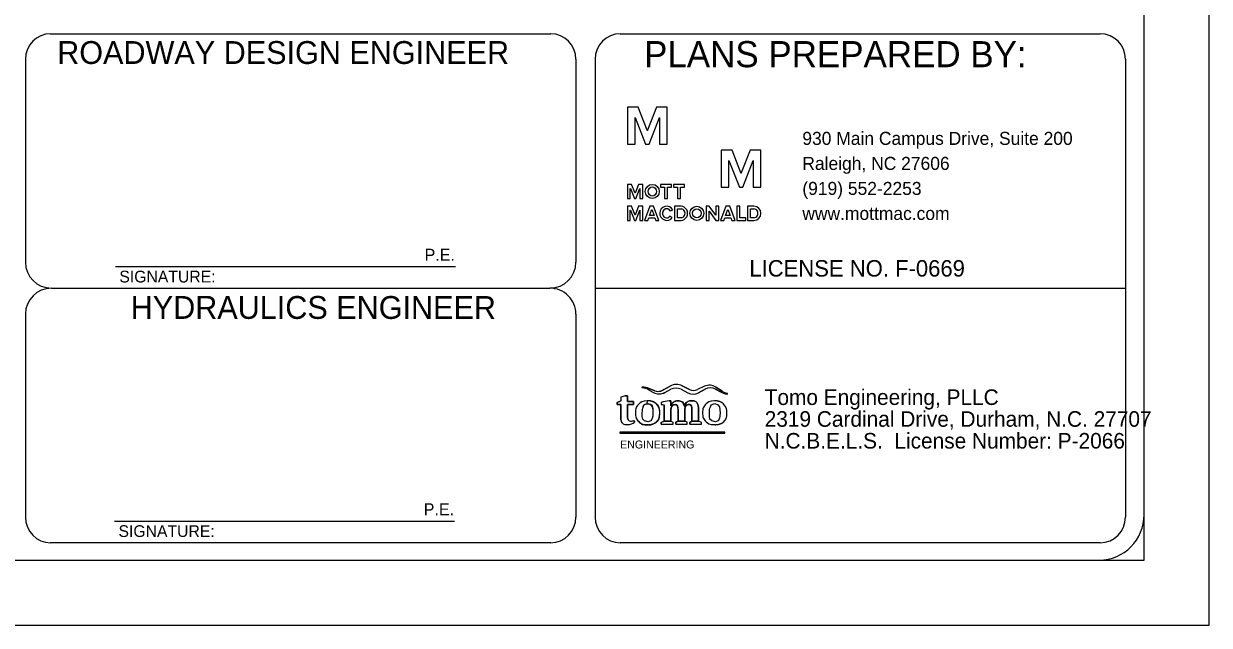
# Model space of a CAD drawing. Extents: x 2538775 to 2540754, y 826823 to 828055.
# Drawn here: x 2540020.2 to 2540474.9, y 826846.8 to 827077.6 of the extents above; entities that cross this region are included whole.
import ezdxf

# ---------------------------------------------------------------- set-up
doc = ezdxf.new("R2010")
doc.units = 0
for name, color, linetype in [('Default', 7, 'Continuous'), ('Old_Level_2', 7, 'Continuous'), ('Old_Level_3', 7, 'Continuous'), ('Old_Level_40', 7, 'Continuous'), ('Old_Level_62', 7, 'Continuous'), ('Old_Level_63', 7, 'Continuous'), ('Sheet Title CELL', 7, 'Continuous')]:
    doc.layers.add(name, color=color, linetype=linetype)

msp = doc.modelspace()

# ---------------------------------------------------------------- linework, layer by layer
at = {"layer": 'Default'}
for p, q in [((2540260.09, 826937.08), (2540261.69, 826936.18)), ((2540260.09, 826937.08), (2540261.69, 826936.18)), ((2540260.12, 826937.66), (2540262.2, 826936.82)), ((2540262.2, 826936.82), (2540260.12, 826937.66)), ((2540265.32, 826937.03), (2540268.13, 826938.62)), ((2540268.13, 826938.62), (2540265.32, 826937.03)), ((2540266.02, 826936.12), (2540268.42, 826937.37)), ((2540266.02, 826936.12), (2540268.42, 826937.37)), ((2540272.33, 826937.38), (2540274.96, 826936.03)), ((2540272.33, 826937.38), (2540274.96, 826936.03)), ((2540272.72, 826938.74), (2540275.53, 826937.33)), ((2540275.53, 826937.33), (2540272.72, 826938.74)), ((2540281.32, 826938.54), (2540278.62, 826937.29)), ((2540281.32, 826938.54), (2540278.62, 826937.29)), ((2540281.52, 826937.39), (2540278.99, 826936.06)), ((2540278.99, 826936.06), (2540281.52, 826937.39)), ((2540287.38, 826936.41), (2540285.57, 826937.38)), ((2540285.57, 826937.38), (2540287.38, 826936.41)), ((2540285.69, 826938.22), (2540288.07, 826936.65)), ((2540288.07, 826936.65), (2540285.69, 826938.22)), ((2540247.86, 826932.3), (2540249.26, 826932.91)), ((2540249.26, 826932.91), (2540247.86, 826932.3)), ((2540249.26, 826934.3), (2540249.26, 826932.91)), ((2540249.26, 826934.3), (2540249.26, 826932.91)), ((2540250.93, 826934.9), (2540251.78, 826934.9)), ((2540251.78, 826934.9), (2540250.93, 826934.9)), ((2540251.78, 826934.9), (2540251.78, 826932.73)), ((2540251.78, 826932.73), (2540251.78, 826934.9)), ((2540251.78, 826932.73), (2540254.05, 826932.73)), ((2540254.05, 826932.73), (2540251.78, 826932.73)), ((2540259.35, 826932.98), (2540259.23, 826931.85)), ((2540259.35, 826932.98), (2540259.35, 826932.98)), ((2540267.76, 826932.92), (2540268.35, 826932.92)), ((2540268.35, 826932.92), (2540267.76, 826932.92)), ((2540268.35, 826932.92), (2540268.35, 826930.98)), ((2540268.35, 826930.98), (2540268.35, 826932.92)), ((2540247.86, 826931.57), (2540247.86, 826932.3)), ((2540247.86, 826932.3), (2540247.86, 826931.57)), ((2540249.24, 826931.57), (2540247.86, 826931.57)), ((2540247.86, 826931.57), (2540249.24, 826931.57)), ((2540249.24, 826925.69), (2540249.24, 826931.57)), ((2540249.24, 826931.57), (2540249.24, 826925.69)), ((2540264.71, 826932.31), (2540264.71, 826931.61)), ((2540264.71, 826932.31), (2540264.71, 826931.61)), ((2540251.14, 826923.82), (2540251.85, 826923.83)), ((2540251.14, 826923.82), (2540251.85, 826923.83)), ((2540254.36, 826925.41), (2540254.48, 826924.81)), ((2540254.48, 826924.81), (2540254.36, 826925.41)), ((2540264.71, 826924.69), (2540265.82, 826925.12)), ((2540265.82, 826925.12), (2540264.71, 826924.69)), ((2540264.71, 826924.01), (2540264.71, 826924.69)), ((2540264.71, 826924.69), (2540264.71, 826924.69)), ((2540264.71, 826924.69), (2540264.71, 826924.01)), ((2540264.71, 826924.01), (2540269.23, 826924.01)), ((2540264.71, 826924.01), (2540269.23, 826924.01)), ((2540268.37, 826925.12), (2540265.82, 826925.12)), ((2540269.23, 826924.69), (2540268.37, 826925.12)), ((2540269.23, 826924.69), (2540268.37, 826925.12)), ((2540269.23, 826924.01), (2540269.23, 826924.69)), ((2540269.23, 826924.69), (2540269.23, 826924.69)), ((2540269.23, 826924.01), (2540269.23, 826924.69)), ((2540270.09, 826924.71), (2540270.09, 826924.71)), ((2540270.27, 826924.71), (2540271.14, 826925.14)), ((2540271.14, 826925.14), (2540270.27, 826924.71)), ((2540270.27, 826924.03), (2540270.27, 826924.71)), ((2540270.27, 826924.71), (2540270.27, 826924.03)), ((2540270.27, 826924.03), (2540274.62, 826924.03)), ((2540270.27, 826924.03), (2540274.62, 826924.03)), ((2540273.7, 826925.14), (2540271.14, 826925.14)), ((2540274.62, 826924.71), (2540273.7, 826925.14)), ((2540274.62, 826924.71), (2540273.7, 826925.14)), ((2540274.62, 826924.03), (2540274.62, 826924.71)), ((2540274.62, 826924.71), (2540274.62, 826924.71)), ((2540274.62, 826924.03), (2540274.62, 826924.71)), ((2540275.39, 826924.68), (2540275.39, 826924.68)), ((2540275.67, 826924.68), (2540276.5, 826925.12)), ((2540276.5, 826925.12), (2540275.67, 826924.68)), ((2540275.67, 826924.01), (2540275.67, 826924.68)), ((2540275.67, 826924.68), (2540275.67, 826924.01)), ((2540275.67, 826924.01), (2540280.19, 826924.01)), ((2540275.67, 826924.01), (2540280.19, 826924.01)), ((2540279.05, 826925.12), (2540276.5, 826925.12)), ((2540280.19, 826924.68), (2540279.05, 826925.12)), ((2540280.19, 826924.68), (2540279.05, 826925.12)), ((2540279.91, 826924.68), (2540279.91, 826924.68)), ((2540280.19, 826924.01), (2540280.19, 826924.68)), ((2540280.19, 826924.01), (2540280.19, 826924.68)), ((2540289.15, 826920.95), (2540248.88, 826920.94)), ((2540289.15, 826920.95), (2540248.88, 826920.94)), ((2540248.88, 826920.94), (2540248.88, 826920.56)), ((2540248.88, 826920.94), (2540248.88, 826920.56)), ((2540248.88, 826920.56), (2540289.15, 826920.56)), ((2540248.88, 826920.56), (2540289.15, 826920.56)), ((2540289.15, 826920.56), (2540289.15, 826920.95)), ((2540289.15, 826920.56), (2540289.15, 826920.95)), ((2540289.15, 826920.56), (2540289.15, 826920.56))]:
    msp.add_line(p, q, dxfattribs=at)
for points in [[(2540254.05, 826932.73), (2540254.05, 826931.57), (2540251.76, 826931.57), (2540251.76, 826926.49)], [(2540251.76, 826926.49), (2540251.76, 826931.57), (2540254.05, 826931.57), (2540254.05, 826932.73)], [(2540268.37, 826929.76), (2540268.37, 826925.12), (2540265.82, 826925.12), (2540265.82, 826931.43)], [(2540265.82, 826931.43), (2540265.82, 826925.12), (2540268.37, 826925.12), (2540268.37, 826929.76)], [(2540273.7, 826929.51), (2540273.7, 826925.14), (2540271.14, 826925.14), (2540271.14, 826929.12)], [(2540271.14, 826929.12), (2540271.14, 826925.14), (2540273.7, 826925.14), (2540273.7, 826929.51)], [(2540279.05, 826929.53), (2540279.05, 826925.12), (2540276.5, 826925.12), (2540276.5, 826929.07)], [(2540276.5, 826929.07), (2540276.5, 826925.12), (2540279.05, 826925.12), (2540279.05, 826929.53)]]:
    msp.add_lwpolyline(points, dxfattribs=at)
for centre, radius, start, end in [((2540257.4, 826938.09), 0.101, 89.4701, 262.0204), ((2540257.4, 826938.09), 0.101, 89.4701, 262.0204), ((2540256.31, 826930.34), 7.72, 60.7255, 82.0204), ((2540256.31, 826930.34), 7.72, 60.7255, 82.0204), ((2540257.33, 826930.67), 7.52, 68.211, 89.4701), ((2540257.33, 826930.67), 7.52, 68.211, 89.4701), ((2540263.54, 826940.18), 3.61, 248.211, 308.9356), ((2540263.54, 826940.18), 3.61, 248.211, 299.5442), ((2540270.54, 826934.37), 4.89, 63.4105, 119.5442), ((2540270.54, 826934.37), 4.89, 63.4105, 119.5442), ((2540270.39, 826933.6), 4.26, 62.7919, 117.5568), ((2540270.39, 826933.6), 4.26, 62.7919, 117.5568), ((2540277.12, 826940.51), 3.56, 243.4105, 294.8953), ((2540277.12, 826940.51), 3.56, 243.4105, 294.8953), ((2540283.21, 826934.47), 4.49, 56.5776, 114.8953), ((2540283.21, 826934.47), 4.49, 56.5776, 114.8953), ((2540283.53, 826933.57), 4.32, 61.9151, 117.8233), ((2540283.53, 826933.57), 4.32, 61.9151, 117.8233), ((2540252.8, 826927.1), 8.02, 103.443, 116.1707), ((2540252.8, 826927.1), 8.02, 103.443, 116.1707), ((2540263.91, 826940.15), 4.55, 240.7255, 299.8298), ((2540263.91, 826940.15), 4.55, 240.7255, 297.5568), ((2540268.26, 826922.63), 10.31, 92.7753, 110.1143), ((2540268.26, 826922.63), 10.31, 92.7753, 110.1143), ((2540276.95, 826939.91), 4.36, 242.7919, 297.8233), ((2540276.95, 826939.91), 4.36, 242.7919, 297.8233), ((2540291.3, 826943.75), 8.32, 241.9151, 260.5433), ((2540291.3, 826943.75), 8.32, 241.9151, 260.5433), ((2540291.34, 826941.6), 5.94, 236.5776, 256.8197), ((2540291.34, 826941.6), 5.94, 236.5776, 256.8197), ((2540289.96, 826935.68), 0.139, 260.5433, 76.8197), ((2540289.96, 826935.68), 0.139, 260.5433, 76.8197), ((2540273.3, 826982.39), 51.51, 260.395, 261.6509), ((2540273.3, 826982.39), 51.51, 260.395, 261.6509), ((2540251.11, 826925.69), 1.86, 180, 270.9178), ((2540251.11, 826925.69), 1.86, 180, 270.9178), ((2540253.23, 826926.49), 1.47, 180, 216.038), ((2540253.23, 826926.49), 1.47, 180, 214.5443), ((2540251.79, 826928.02), 4.19, 270.9178, 309.9754), ((2540251.79, 826928.02), 4.19, 270.9178, 309.9754), ((2540252.89, 826926.25), 1.04, 214.2431, 269.2019), ((2540252.89, 826926.25), 1.04, 214.2431, 269.2019), ((2540252.94, 826930.15), 4.95, 269.2019, 286.6975), ((2540252.94, 826930.15), 4.95, 269.2019, 286.6975)]:
    msp.add_arc(centre, radius, start, end, dxfattribs=at)
for points, degree in [([(2540259.35, 826932.98), (2540261.23, 826932.98), (2540262.71, 826931.94), (2540264.13, 826930.56), (2540264.13, 826928.32), (2540264.1, 826925.83), (2540262.7, 826924.69), (2540261.18, 826923.69), (2540259.35, 826923.82), (2540257.36, 826923.69), (2540256.1, 826924.98), (2540254.84, 826926.28), (2540254.84, 826928.34), (2540254.84, 826930.44), (2540256.13, 826931.71), (2540257.42, 826932.98), (2540259.35, 826932.98)], 3), ([(2540259.35, 826932.98), (2540257.42, 826932.98), (2540256.13, 826931.71), (2540254.84, 826930.44), (2540254.84, 826928.34), (2540254.84, 826926.28), (2540256.1, 826924.98), (2540257.36, 826923.69), (2540259.35, 826923.82)], 3), ([(2540262.71, 826931.94), (2540261.23, 826932.98), (2540259.35, 826932.98)], 2), ([(2540268.35, 826930.98), (2540269.08, 826932.88), (2540271.15, 826932.95), (2540273.19, 826932.8), (2540273.57, 826930.89), (2540274.4, 826932.93), (2540276.46, 826932.97), (2540278.03, 826932.92), (2540278.63, 826931.84), (2540279.07, 826930.97), (2540279.05, 826929.53)], 3), ([(2540271.15, 826932.95), (2540269.08, 826932.88), (2540268.35, 826930.98)], 2), ([(2540273.57, 826930.89), (2540273.19, 826932.8), (2540271.15, 826932.95)], 2), ([(2540279.05, 826929.53), (2540279.07, 826930.97), (2540278.63, 826931.84), (2540278.03, 826932.92), (2540276.46, 826932.97), (2540274.4, 826932.93), (2540273.57, 826930.89)], 3), ([(2540285.1, 826932.98), (2540283.17, 826932.98), (2540281.88, 826931.71), (2540280.59, 826930.44), (2540280.59, 826928.34), (2540280.59, 826926.28), (2540281.85, 826924.98), (2540283.12, 826923.69), (2540285.1, 826923.82)], 3), ([(2540288.46, 826931.94), (2540286.98, 826932.98), (2540285.1, 826932.98)], 2), ([(2540259.7, 826924.84), (2540257.25, 826925.04), (2540257.46, 826928.37), (2540257.46, 826929.69), (2540257.73, 826930.5), (2540258.18, 826931.77), (2540259.52, 826931.89)], 3), ([(2540259.7, 826924.84), (2540261.52, 826925.2), (2540261.43, 826928.42), (2540261.59, 826931.51), (2540259.52, 826931.89), (2540258.18, 826931.77), (2540257.73, 826930.5), (2540257.46, 826929.69), (2540257.46, 826928.37), (2540257.25, 826925.04), (2540259.7, 826924.84)], 3), ([(2540259.52, 826931.89), (2540261.59, 826931.51), (2540261.43, 826928.42), (2540261.52, 826925.2), (2540259.7, 826924.84)], 3), ([(2540262.7, 826924.69), (2540264.1, 826925.83), (2540264.13, 826928.32), (2540264.13, 826930.56), (2540262.71, 826931.94)], 3), ([(2540271.14, 826929.12), (2540271.17, 826930.22), (2540270.96, 826930.72), (2540270.85, 826931.52), (2540269.91, 826931.52), (2540268.64, 826931.33), (2540268.37, 826929.76)], 3), ([(2540268.37, 826929.76), (2540268.64, 826931.33), (2540269.91, 826931.52)], 2), ([(2540269.91, 826931.52), (2540270.85, 826931.52), (2540270.96, 826930.72)], 2), ([(2540270.96, 826930.72), (2540271.17, 826930.22), (2540271.14, 826929.12)], 2), ([(2540276.5, 826929.07), (2540276.5, 826929.94), (2540276.4, 826930.35), (2540276.22, 826931.51), (2540275.25, 826931.51), (2540273.83, 826931.39), (2540273.7, 826929.51)], 3), ([(2540273.7, 826929.51), (2540273.83, 826931.39), (2540275.25, 826931.51), (2540276.22, 826931.51), (2540276.4, 826930.35), (2540276.5, 826929.94), (2540276.5, 826929.07)], 3), ([(2540285.46, 826924.84), (2540283.01, 826925.04), (2540283.22, 826928.37), (2540283.22, 826929.69), (2540283.49, 826930.5), (2540283.93, 826931.77), (2540285.28, 826931.89)], 3), ([(2540285.28, 826931.89), (2540287.34, 826931.51), (2540287.18, 826928.42), (2540287.27, 826925.2), (2540285.46, 826924.84)], 3), ([(2540288.46, 826924.69), (2540289.85, 826925.83), (2540289.88, 826928.32), (2540289.89, 826930.56), (2540288.46, 826931.94)], 3), ([(2540259.35, 826923.82), (2540261.18, 826923.69), (2540262.7, 826924.69)], 2), ([(2540285.1, 826923.82), (2540286.94, 826923.69), (2540288.46, 826924.69)], 2)]:
    msp.add_open_spline(points, degree=degree, dxfattribs=at)
at = {"layer": 'Old_Level_2'}
for p, q in [((2540255.92, 827045.56), (2540251.73, 827045.56)), ((2540251.73, 827045.56), (2540251.73, 827031.43)), ((2540259.34, 827036.83), (2540255.92, 827045.56)), ((2540262.84, 827045.56), (2540259.42, 827036.83)), ((2540260.03, 827031.43), (2540264, 827041.63)), ((2540267.03, 827045.56), (2540262.84, 827045.56)), ((2540264, 827041.63), (2540264.05, 827041.63)), ((2540264.05, 827041.63), (2540264.05, 827031.43)), ((2540267.03, 827031.43), (2540267.03, 827045.56)), ((2540254.71, 827031.43), (2540254.71, 827041.59)), ((2540254.71, 827041.59), (2540254.75, 827041.59)), ((2540254.75, 827041.59), (2540258.73, 827031.43)), ((2540259.33, 827036.7), (2540259.34, 827036.83)), ((2540259.42, 827036.7), (2540259.33, 827036.7)), ((2540259.42, 827036.83), (2540259.42, 827036.7)), ((2540251.73, 827031.43), (2540254.71, 827031.43)), ((2540258.73, 827031.43), (2540260.03, 827031.43)), ((2540264.05, 827031.43), (2540267.03, 827031.43)), ((2540291.85, 827029.1), (2540287.66, 827029.1)), ((2540287.66, 827029.1), (2540287.66, 827014.97)), ((2540295.27, 827020.37), (2540291.85, 827029.1)), ((2540298.77, 827029.1), (2540295.35, 827020.37)), ((2540302.96, 827029.1), (2540298.77, 827029.1)), ((2540302.96, 827014.97), (2540302.96, 827029.1)), ((2540290.64, 827014.97), (2540290.64, 827025.12)), ((2540290.64, 827025.12), (2540290.69, 827025.12)), ((2540290.69, 827025.12), (2540294.66, 827014.97)), ((2540295.96, 827014.97), (2540299.94, 827025.17)), ((2540299.94, 827025.17), (2540299.98, 827025.17)), ((2540299.98, 827025.17), (2540299.98, 827014.97)), ((2540295.27, 827020.24), (2540295.27, 827020.37)), ((2540295.35, 827020.24), (2540295.27, 827020.24)), ((2540295.35, 827020.37), (2540295.35, 827020.24)), ((2540253.33, 827015.96), (2540251.73, 827015.96)), ((2540251.73, 827015.96), (2540251.73, 827010.56)), ((2540252.85, 827010.56), (2540252.85, 827014.45)), ((2540252.85, 827014.45), (2540252.9, 827014.45)), ((2540252.85, 827014.45), (2540252.9, 827014.45)), ((2540252.9, 827014.45), (2540254.41, 827010.56)), ((2540254.67, 827012.59), (2540253.33, 827015.96)), ((2540256.01, 827015.96), (2540254.67, 827012.59)), ((2540254.93, 827010.56), (2540256.44, 827014.45)), ((2540257.61, 827015.96), (2540256.01, 827015.96)), ((2540256.44, 827014.45), (2540256.48, 827014.45)), ((2540256.44, 827014.45), (2540256.48, 827014.45)), ((2540256.44, 827014.45), (2540256.48, 827014.45)), ((2540256.48, 827014.45), (2540256.48, 827010.56)), ((2540257.61, 827010.56), (2540257.61, 827015.96)), ((2540257.61, 827010.56), (2540257.61, 827015.96)), ((2540287.66, 827014.97), (2540290.64, 827014.97)), ((2540294.66, 827014.97), (2540295.96, 827014.97)), ((2540299.98, 827014.97), (2540302.96, 827014.97)), ((2540251.73, 827010.56), (2540252.85, 827010.56)), ((2540254.41, 827010.56), (2540254.93, 827010.56)), ((2540256.48, 827010.56), (2540257.61, 827010.56)), ((2540253.33, 827007.58), (2540251.73, 827007.58)), ((2540251.73, 827007.58), (2540251.73, 827002.18)), ((2540252.85, 827002.18), (2540252.85, 827006.07)), ((2540252.85, 827006.07), (2540252.9, 827006.07)), ((2540252.9, 827006.07), (2540254.41, 827002.18)), ((2540254.67, 827004.21), (2540253.33, 827007.58)), ((2540256.01, 827007.58), (2540254.67, 827004.21)), ((2540254.93, 827002.18), (2540256.44, 827006.07)), ((2540257.61, 827007.58), (2540256.01, 827007.58)), ((2540256.44, 827006.07), (2540256.48, 827006.07)), ((2540256.48, 827006.07), (2540256.48, 827002.18)), ((2540257.61, 827002.18), (2540257.61, 827007.58)), ((2540268.15, 827005.82), (2540269.1, 827006.25)), ((2540268.15, 827005.82), (2540269.1, 827006.25)), ((2540272.3, 827007.57), (2540269.83, 827007.58)), ((2540269.83, 827007.58), (2540269.83, 827004.78)), ((2540270.96, 827003.21), (2540270.96, 827006.58)), ((2540270.96, 827006.58), (2540272.3, 827006.58)), ((2540297.79, 827007.58), (2540297.79, 827007.58)), ((2540300.26, 827007.58), (2540297.79, 827007.58)), ((2540297.79, 827007.58), (2540297.79, 827004.78)), ((2540298.92, 827003.21), (2540298.92, 827006.58)), ((2540298.92, 827006.58), (2540300.26, 827006.58)), ((2540300.26, 827006.54), (2540300.26, 827006.54)), ((2540251.73, 827002.18), (2540252.85, 827002.18)), ((2540254.41, 827002.18), (2540254.93, 827002.18)), ((2540256.48, 827002.18), (2540257.61, 827002.18)), ((2540268.95, 827003.29), (2540268.02, 827003.74)), ((2540268.95, 827003.29), (2540268.02, 827003.74)), ((2540269.83, 827004.78), (2540269.83, 827002.18)), ((2540269.83, 827002.18), (2540272.3, 827002.18)), ((2540272.3, 827003.21), (2540270.96, 827003.21)), ((2540297.79, 827004.78), (2540297.79, 827002.18)), ((2540297.79, 827002.18), (2540300.26, 827002.18)), ((2540300.26, 827003.21), (2540298.92, 827003.21))]:
    msp.add_line(p, q, dxfattribs=at)
for points in [[(2540264.39, 827014.97), (2540265.95, 827014.97), (2540265.95, 827010.56), (2540267.11, 827010.56), (2540267.11, 827014.97), (2540268.67, 827014.97), (2540268.67, 827015.96), (2540264.39, 827015.96), (2540264.39, 827014.97)], [(2540269.36, 827014.97), (2540270.92, 827014.97), (2540270.92, 827010.56), (2540272.08, 827010.56), (2540272.08, 827014.97), (2540273.64, 827014.97), (2540273.64, 827015.96), (2540269.36, 827015.96), (2540269.36, 827014.97)], [(2540258.26, 827002.18), (2540259.55, 827002.18), (2540259.9, 827003.09), (2540262.23, 827003.09), (2540262.58, 827002.18), (2540263.83, 827002.18), (2540261.76, 827007.58), (2540260.33, 827007.58), (2540258.26, 827002.18)], [(2540260.2, 827004.08), (2540261.07, 827006.41), (2540261.93, 827004.08), (2540260.2, 827004.08)], [(2540283.06, 827005.68), (2540283.1, 827005.68), (2540285.7, 827002.18), (2540286.78, 827002.18), (2540286.78, 827007.58), (2540285.65, 827007.58), (2540285.65, 827004.16), (2540283.1, 827007.58), (2540281.98, 827007.58), (2540281.98, 827002.18), (2540283.06, 827002.18), (2540283.06, 827005.68)], [(2540287.47, 827002.18), (2540288.76, 827002.18), (2540289.11, 827003.09), (2540291.44, 827003.09), (2540291.79, 827002.18), (2540293.04, 827002.18), (2540290.97, 827007.58), (2540289.54, 827007.58), (2540287.47, 827002.18)], [(2540289.41, 827004.08), (2540290.28, 827006.41), (2540291.14, 827004.08), (2540289.41, 827004.08)], [(2540297.15, 827002.18), (2540297.15, 827003.13), (2540294.81, 827003.13), (2540294.81, 827007.58), (2540293.69, 827007.58), (2540293.69, 827002.18), (2540297.15, 827002.18)], [(2540297.15, 827002.18), (2540297.15, 827003.13), (2540294.81, 827003.13), (2540294.81, 827007.58), (2540293.69, 827007.58), (2540293.69, 827002.18), (2540297.15, 827002.18), (2540297.15, 827003.13)]]:
    msp.add_lwpolyline(points, dxfattribs=at)
msp.add_arc((2540300.26, 827004.88), 2.7, 270, 90, dxfattribs=at)
for centre, major_axis, ratio in [((2540261.28, 827013.26), (0, 2.7), 0.993118), ((2540261.28, 827013.26), (0, 1.76), 0.916103), ((2540278.35, 827004.88), (0, 2.7), 0.993118), ((2540278.35, 827004.88), (0, 1.76), 0.916103)]:
    msp.add_ellipse(centre, major_axis=major_axis, ratio=ratio, dxfattribs=at)
for centre, major_axis, ratio, start_param, end_param in [((2540266.79, 827004.88), (0, 2.7), 0.993118, 5.246647, 10.366427), ((2540266.79, 827004.88), (0, 2.7), 0.993118, 5.246647, 10.366427), ((2540266.79, 827004.88), (0, 1.76), 0.916103, 5.276876, 9.424778), ((2540266.79, 827004.88), (0, 1.76), 0.916103, 5.276876, 10.296021), ((2540272.3, 827004.88), (0, -2.7), 0.930276, 0, 3.141593), ((2540272.3, 827004.9), (0, -1.69), 0.900832, 0, 3.141593), ((2540300.26, 827004.9), (0, -1.69), 0.900832, 0, 3.141593), ((2540266.79, 827004.88), (0, 1.76), 0.916103, 3.141593, 4.012835)]:
    msp.add_ellipse(centre, major_axis=major_axis, ratio=ratio, start_param=start_param, end_param=end_param, dxfattribs=at)
at = {"layer": 'Old_Level_40'}
for p, q in [((2540449.9, 826889.31), (2540449.9, 827407.64)), ((2540030.52, 827073.79), (2540222.32, 827073.79)), ((2540249.01, 827073.79), (2540433.08, 827073.79)), ((2540020.85, 827063.98), (2540020.85, 826986.15)), ((2540231.99, 827063.98), (2540231.99, 826986.15)), ((2540239.34, 827063.98), (2540239.34, 826888.33)), ((2540442.74, 827063.98), (2540442.74, 826888.33)), ((2540030.84, 826976.16), (2540222, 826976.16)), ((2540239.34, 826976.16), (2540442.74, 826976.16)), ((2540020.85, 826966.17), (2540020.85, 826888.33)), ((2540231.99, 826966.17), (2540231.99, 826888.33)), ((2540222.32, 826878.52), (2540030.51, 826878.52)), ((2540433.07, 826878.52), (2540249, 826878.52))]:
    msp.add_line(p, q, dxfattribs=at)
msp.add_lwpolyline([(2538967.11, 826871.85), (2540432.69, 826871.85)], dxfattribs=at)
for centre, start, end in [((2540030.84, 826986.15), 180, 270), ((2540222, 826986.15), 270, 359.9996), ((2540030.84, 826966.17), 90, 180), ((2540222, 826966.17), 359.9996, 90)]:
    msp.add_arc(centre, 9.99, start, end, dxfattribs=at)
for centre, major_axis, start_param, end_param in [((2540030.52, 827063.98), (0, 9.81), 0, 1.570796), ((2540222.32, 827063.98), (0, 9.81), 4.712389, 6.282258), ((2540249.01, 827063.98), (0, 9.81), 0, 1.570796), ((2540433.07, 827063.98), (0, 9.81), 4.712389, 6.282258), ((2540030.52, 826888.33), (0, -9.81), 4.712389, 6.283185), ((2540222.32, 826888.33), (0, 9.81), 3.141593, 4.712389), ((2540249.01, 826888.33), (0, -9.81), 4.712389, 6.283185), ((2540432.69, 826889.31), (0, 17.47), 3.141593, 4.712389), ((2540433.07, 826888.33), (0, 9.81), 3.141593, 4.712389)]:
    msp.add_ellipse(centre, major_axis=major_axis, ratio=0.985213, start_param=start_param, end_param=end_param, dxfattribs=at)
at = {"layer": 'Old_Level_62'}
msp.add_lwpolyline([(2538799.9, 826871.85), (2540449.9, 826871.85), (2540449.9, 827921.85), (2538799.9, 827921.85)], close=True, dxfattribs=at)
at = {"layer": 'Old_Level_63'}
msp.add_lwpolyline([(2538774.9, 826846.85), (2540474.9, 826846.85), (2540474.9, 827946.85), (2538774.9, 827946.85)], close=True, dxfattribs=at)
at = {"layer": 'Sheet Title CELL'}
for p, q in [((2540055.37, 826984.49), (2540185.76, 826984.49)), ((2540055.05, 826886.85), (2540185.44, 826886.85))]:
    msp.add_line(p, q, dxfattribs=at)

# ---------------------------------------------------------------- texts
at = {"layer": 'Old_Level_2'}
for s, p in [('930 Main Campus Drive, Suite 200', (2540318.82, 827031.13)), ('Raleigh, NC 27606', (2540318.82, 827021.53)), ('(919) 552-2253', (2540318.82, 827011.93)), ('www.mottmac.com', (2540318.82, 827002.33))]:
    msp.add_text(s, height=5, rotation=360, dxfattribs=at).set_placement(p)
at = {"layer": 'Old_Level_3'}
for s, height, rotation, p in [('Tomo Engineering, PLLC', 5.9773, 0.0019, (2540304.38, 826931.36)), ('2319 Cardinal Drive, Durham, N.C. 27707', 5.9773, 0.0004, (2540304.38, 826923)), ('N.C.B.E.L.S.  License Number: P-2066', 5.9773, 0.0004, (2540304.38, 826914.64)), ('ENGINEERING', 3.0404, 0.0004, (2540248.95, 826914.68))]:
    msp.add_text(s, height=height, rotation=rotation, dxfattribs=at).set_placement(p)
at = {"layer": 'Old_Level_40'}
msp.add_text('PLANS PREPARED BY:', height=10.0231, rotation=360, dxfattribs=at).set_placement((2540258.12, 827060.93))
at = {"layer": 'Sheet Title CELL'}
for s, height, rotation, p in [(' ROADWAY DESIGN ENGINEER', 8.7691, 360, (2540029.78, 827062.18)), (' ROADWAY DESIGN ENGINEER', 8.7691, 360, (2540029.78, 827062.18)), (' ROADWAY DESIGN ENGINEER', 8.7691, 360, (2540029.78, 827062.18)), ('P.E.', 4.607, 359.9851, (2540173.92, 826986.67)), ('SIGNATURE:', 4.515, 359.9851, (2540056.87, 826978.36)), ('LICENSE NO. F-0669', 6.3215, 359.9851, (2540298.49, 826980.63)), ('HYDRAULICS ENGINEER', 8.7691, 359.9851, (2540061.22, 826964.4)), ('P.E.', 4.607, 359.9851, (2540173.6, 826889.03)), ('SIGNATURE:', 4.515, 359.9851, (2540056.55, 826880.72))]:
    msp.add_text(s, height=height, rotation=rotation, dxfattribs=at).set_placement(p)

doc.saveas('drawing.dxf')
